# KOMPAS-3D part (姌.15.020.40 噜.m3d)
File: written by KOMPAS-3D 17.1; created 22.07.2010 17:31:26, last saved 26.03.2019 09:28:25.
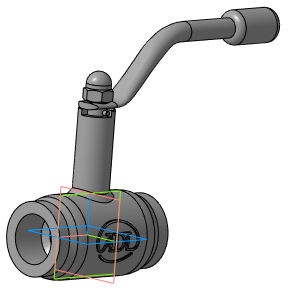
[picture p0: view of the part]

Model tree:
1. Плоскость XY
2. Плоскость ZX
3. Плоскость ZY
4. Ось X
5. Ось Y
6. Ось Z
7. Начало координат
8. Операция без истории:2  (labels: Сталь 20  ГОСТ 1050-88)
